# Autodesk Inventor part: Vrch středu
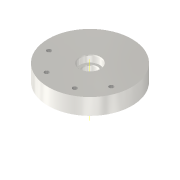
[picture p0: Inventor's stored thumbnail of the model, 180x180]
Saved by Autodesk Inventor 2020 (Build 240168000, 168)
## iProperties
Created: 2025-03
Part Number: Vrch středu
Material: Ocel
Document SubType Name: Modeling
Designer: doma
Density: 7.85 g/cm^3
Appearance: Ocel
Mass: 1963.34 g
Surface Area: 395.068 cm^2
Volume: 250.106 cm^3
Author: doma
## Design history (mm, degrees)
sketch "Náčrt1"
  geometry: L1 (61.916, 28.694)-(61.916, 11.787); L2 (15.916, 12.789)-(46.916, 12.789); L3 (-2.084, 7.789)-(-2.084, 32.789); L4 (-2.084, 32.789)-(46.916, 32.789); L5 (46.916, 32.789)-(46.916, 12.789); L6 (15.916, 12.789)-(2.916, 12.789); L7 (2.916, 12.789)-(2.916, 7.789); L8 (2.916, 7.789)-(-2.084, 7.789); L9 (-2.084, 7.789)-(-2.084, 7.789)
  constraints: 18 end point, 5 perpendicular, 2 horizontal, 2 vertical
  dimensions: "d6" = 25 distance of L3.start L3.end; "d7" = 64 distance between parallel lines of L1 L3; "d11" = 15 distance between parallel lines of L1 L5; "d13" = 5 distance between parallel lines of L6 L8; "d14" = 20 distance of L4.end L2.end; "d15" = 5 distance between parallel lines of L7 L9
revolve "Rotace1" sketch "Náčrt1" stored, may be unused: angle "d12" = 90 deg
node "Pracovní osa1"
sketch "Náčrt2"
  geometry: A1 r 50 centre (0, 0) between (21.794, -45) and (47.697, -15) reference; 3 further points
  constraints: 4 point on circle, 1 centre point, 1 other
  dimensions: "d18" = 15 vertical distance of A1.end A1.centre; "d19" = 45 vertical distance of A1.centre A1.start
hole "Díra1" sketch "Náčrt2" at (21.794, -45), (47.697, -15), (-20.786, -45.475), (-47.697, -15) diameter "d20" = 6.647; stored, may be unused: countersink angle "d24" = 90 deg, drill point angle "d26" = 118 deg; dims "d21" = 16, "d22" = 4, "d23" = 2, "d25" = 8
sketch "Náčrt3"
  geometry: C1 r 10 at (0, 0); C2 r 15 at (0, 0) reference; 1 further point
  constraints: 1 centre point
  dimensions: "d27" = 20 diameter of C1
extrude "Vysunutí1" join sketch "Náčrt3" distance "d28" = 10; taper "d29" = 0 deg
chamfer "Zkosení1" distance "d30" = 1; stored, may be unused: second distance "d31" = 2, angle "d32" = 45 deg
fillet "Zaoblení1" dims "d33" = 0.2
chamfer "Zkosení2" distance "d34" = 1; stored, may be unused: second distance "d35" = 2, angle "d36" = 45 deg
fillet "Zaoblení2" dims "d37" = 0.2
node "Těleso1"
